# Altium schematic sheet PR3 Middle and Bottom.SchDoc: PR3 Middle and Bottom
size C; Organization: LIGO Laboratory; Address1: California Institute of Technology; Address2: Massachusetts Institute of Technology; DocumentNumber: D0902810; Revision: v10; SheetNumber: 6; SheetTotal: 14; Engineer: J.Kissel/L.Sánchez
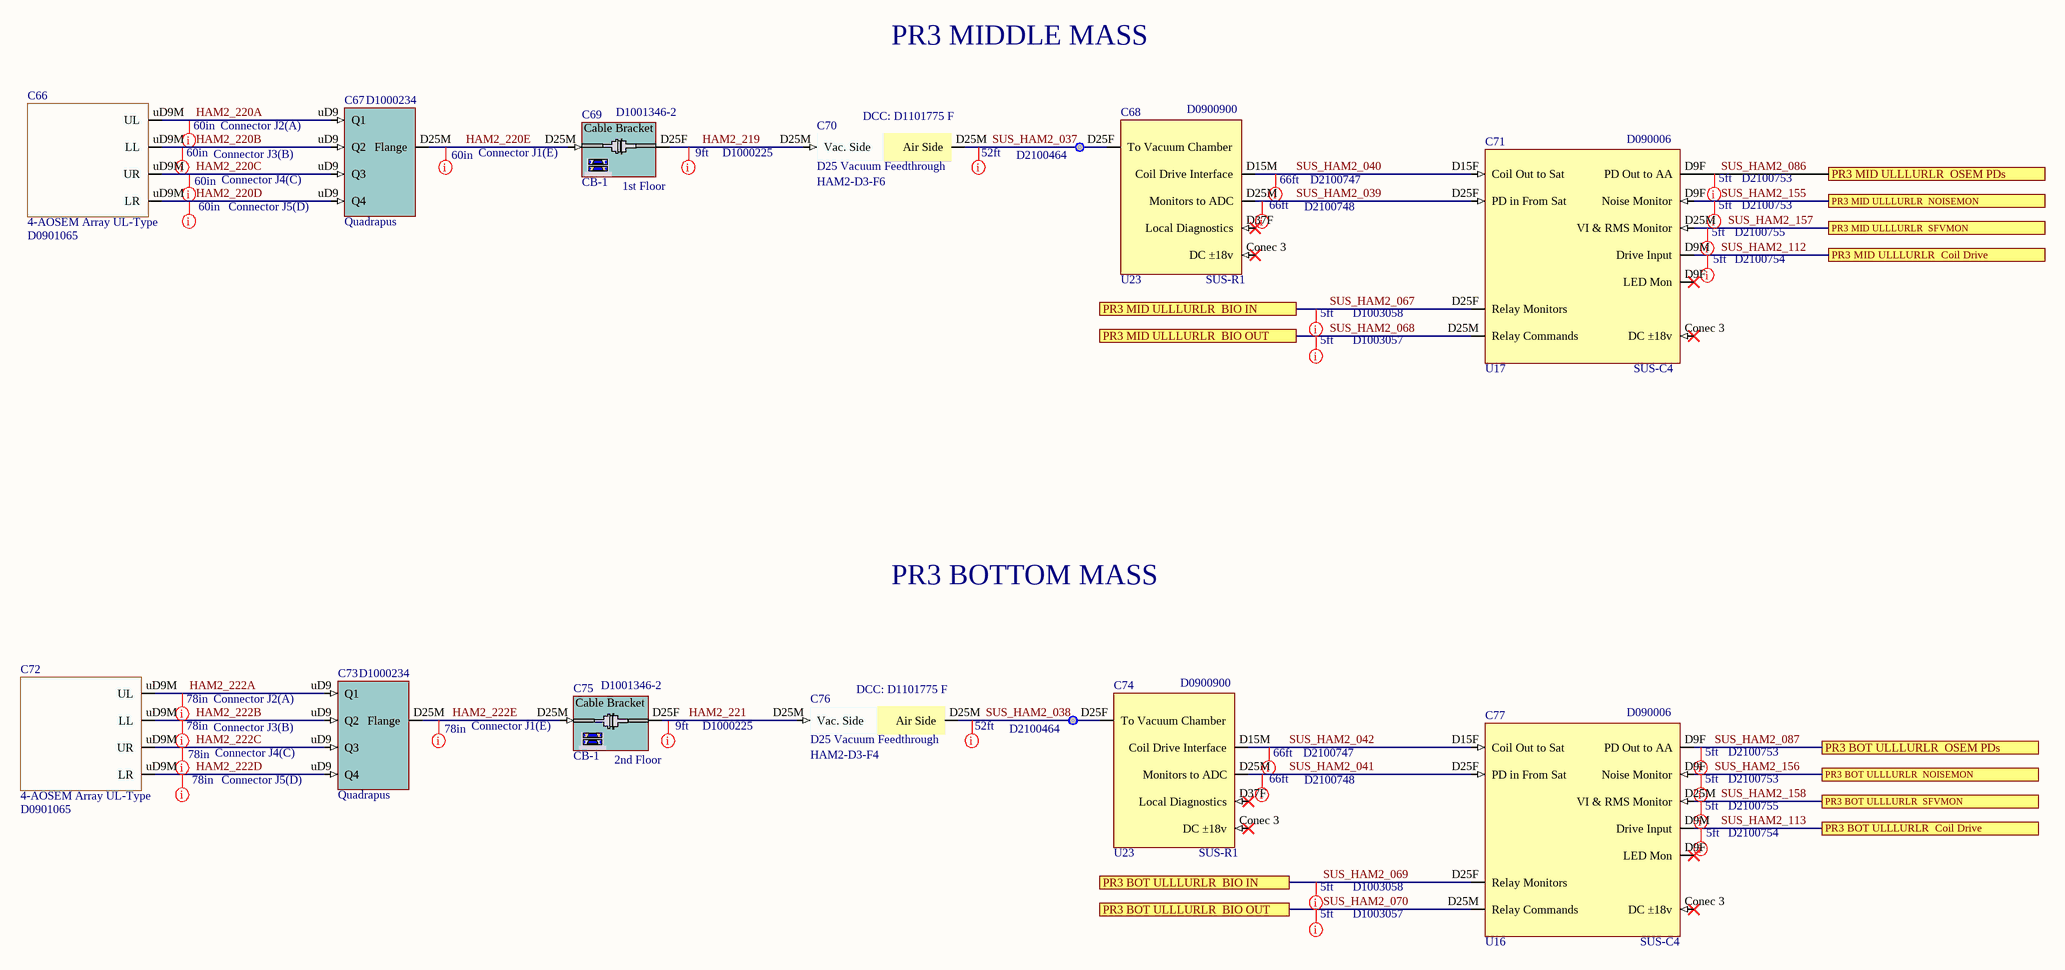
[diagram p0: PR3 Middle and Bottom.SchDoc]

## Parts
C66  4-AOSEM Array UL-Type  DCC: D0901065
C67  Quadrapus  DCC: D1000234
C68  Slot: U23  Rack: SUS-R1  DCC: D0900900  (hidden comment: Satellite Amplifier UK D0900900)
C69  Rack: CB-1  Slot: 1st Floor  DCC: D1001346-2  (hidden comment: Cable Bracket)
C70  D25 Vacuum Feedthrough  value HAM2-D3-F6  DCC: D1101775 F
C71  Slot: U17  Rack: SUS-C4  DCC: D090006  (hidden comment: CD Triple Acq D090006)
C72  4-AOSEM Array UL-Type  DCC: D0901065
C73  Quadrapus  DCC: D1000234
C74  Slot: U23  Rack: SUS-R1  DCC: D0900900  (hidden comment: Satellite Amplifier UK D0900900)
C75  Rack: CB-1  Slot: 2nd Floor  DCC: D1001346-2  (hidden comment: Cable Bracket)
C76  D25 Vacuum Feedthrough  value HAM2-D3-F4  DCC: D1101775 F
C77  Slot: U16  Rack: SUS-C4  DCC: D090006  (hidden comment: CD Triple Acq D090006)

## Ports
PR3 BOT ULLLURLR  BIO IN, PR3 BOT ULLLURLR  BIO OUT, PR3 BOT ULLLURLR  Coil Drive, PR3 BOT ULLLURLR  NOISEMON, PR3 BOT ULLLURLR  OSEM PDs, PR3 BOT ULLLURLR  SFVMON, PR3 MID ULLLURLR  BIO IN, PR3 MID ULLLURLR  BIO OUT, PR3 MID ULLLURLR  Coil Drive, PR3 MID ULLLURLR  NOISEMON, PR3 MID ULLLURLR  OSEM PDs, PR3 MID ULLLURLR  SFVMON

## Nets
HAM2_219: C69.D25F C70.D25M(Vac._Side)
HAM2_220A: C66.uD9M(UL) C67.uD9(Q1)
HAM2_220B: C66.uD9M(LL) C67.uD9(Q2)
HAM2_220C: C66.uD9M(UR) C67.uD9(Q3)
HAM2_220D: C66.uD9M(LR) C67.uD9(Q4)
HAM2_220E: C67.D25M(Flange) C69.D25M
HAM2_221: C75.D25F C76.D25M(Vac._Side)
HAM2_222A: C72.uD9M(UL) C73.uD9(Q1)
HAM2_222B: C72.uD9M(LL) C73.uD9(Q2)
HAM2_222C: C72.uD9M(UR) C73.uD9(Q3)
HAM2_222D: C72.uD9M(LR) C73.uD9(Q4)
HAM2_222E: C73.D25M(Flange) C75.D25M
SUS_HAM2_037: C68.D25F(To_Vacuum_Chamber) C70.D25M(Air_Side)
SUS_HAM2_038: C74.D25F(To_Vacuum_Chamber) C76.D25M(Air_Side)
SUS_HAM2_039: C68.D25M(Monitors_to_ADC) C71.D25F(PD_in_From_Sat)
SUS_HAM2_040: C68.D15M(Coil_Drive_Interface) C71.D15F(Coil_Out_to_Sat)
SUS_HAM2_041: C74.D25M(Monitors_to_ADC) C77.D25F(PD_in_From_Sat)
SUS_HAM2_042: C74.D15M(Coil_Drive_Interface) C77.D15F(Coil_Out_to_Sat)
SUS_HAM2_067: C71.D25F(Relay_Monitors) ; port PR3 MID ULLLURLR  BIO IN
SUS_HAM2_068: C71.D25M(Relay_Commands) ; port PR3 MID ULLLURLR  BIO OUT
SUS_HAM2_069: C77.D25F(Relay_Monitors) ; port PR3 BOT ULLLURLR  BIO IN
SUS_HAM2_070: C77.D25M(Relay_Commands) ; port PR3 BOT ULLLURLR  BIO OUT
SUS_HAM2_086: C71.D9F(PD_Out_to_AA) ; port PR3 MID ULLLURLR  OSEM PDs
SUS_HAM2_087: C77.D9F(PD_Out_to_AA) ; port PR3 BOT ULLLURLR  OSEM PDs
SUS_HAM2_112: C71.D9M(Drive_Input) ; port PR3 MID ULLLURLR  Coil Drive
SUS_HAM2_113: C77.D9M(Drive_Input) ; port PR3 BOT ULLLURLR  Coil Drive
SUS_HAM2_155: C71.D9F(Noise_Monitor) ; port PR3 MID ULLLURLR  NOISEMON
SUS_HAM2_156: C77.D9F(Noise_Monitor) ; port PR3 BOT ULLLURLR  NOISEMON
SUS_HAM2_157: C71.D25M(VI_&_RMS_Monitor) ; port PR3 MID ULLLURLR  SFVMON
SUS_HAM2_158: C77.D25M(VI_&_RMS_Monitor) ; port PR3 BOT ULLLURLR  SFVMON

Not connected (* = marked no-connect by the designer): C68 Conec 3(DC_±18v)* D37F(Local_Diagnostics)*; C71 Conec 3(DC_±18v)*; C74 Conec 3(DC_±18v)* D37F(Local_Diagnostics)*; C77 Conec 3(DC_±18v)*

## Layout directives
Length: 52ft; DCC: D2100464: SUS_HAM2_037, SUS_HAM2_038
Length: 5ft; DCC: D2100753: SUS_HAM2_086, SUS_HAM2_087, SUS_HAM2_155, SUS_HAM2_156
Length: 5ft; DCC: D2100754: SUS_HAM2_112, SUS_HAM2_113
Length: 5ft; DCC: D2100755: SUS_HAM2_157, SUS_HAM2_158
Length: 60in; DCC: Connector J5(D): HAM2_220D
Length: 60in; DCC: Connector J4(C): HAM2_220C
Length: 60in; DCC: Connector J3(B): HAM2_220B
Length: 60in; DCC: Connector J2(A): HAM2_220A
Length: 66ft; DCC: D2100747: SUS_HAM2_040, SUS_HAM2_042
Length: 66ft; DCC: D2100748: SUS_HAM2_039, SUS_HAM2_041
Length: 5ft; DCC: D1003058: SUS_HAM2_067, SUS_HAM2_069
Length: 5ft; DCC: D1003057: SUS_HAM2_068, SUS_HAM2_070
Length: 9ft; DCC: D1000225: HAM2_219, HAM2_221
Length: 78in; DCC: Connector J5(D): HAM2_222D
Length: 78in; DCC: Connector J4(C): HAM2_222C
Length: 78in; DCC: Connector J3(B): HAM2_222B
Length: 78in; DCC: Connector J2(A): HAM2_222A
Length: 60in; DCC: Connector J1(E): HAM2_220E
Length: 78in; DCC: Connector J1(E): HAM2_222E

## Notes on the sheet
- PR3 MIDDLE MASS
- PR3 BOTTOM MASS

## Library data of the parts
C66 C72 = 4-AOSEM Array UL-Type: Rack: R?; Slot: U?; Serial: Sxxxxxxx; System: SUS
C67 C73 = D1000234 D25 Quadrapus: Slot: U?; Rack: R?; Serial: Sxxxxxxx; System: SUS
C68 C74 = Satellite Amplifier UK D0900900: System: SUS; Serial: Sxxxxxxx
C69 = D1001346-2 1st Cable Bracket: D1001346-2 1/2 Cable Bracket for HAM Tables; Serial: Sxxxxxxx; System: SUS
C70 C76 = VacFeedD25: Serial: Sxxxxxxx; System: ISC; Rack: R?; Slot: U?
C71 C77 = CD Triple Acq D090006: System: SUS; Serial: Sxxxxxxx
C75 = D1001346-2 2nd Cable Bracket: D1001346-2 2/2 Cable Bracket for HAM Tables; Serial: Sxxxxxxx; System: SUS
